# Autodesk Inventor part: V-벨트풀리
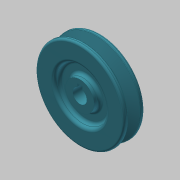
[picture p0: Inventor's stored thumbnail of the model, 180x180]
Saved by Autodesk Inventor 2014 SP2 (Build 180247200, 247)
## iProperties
Created: 2019-09
Part Number: V-벨트풀리
Material: 알루미늄 6061
Document SubType Name: Modeling
Designer: mduedu
Density: 1 g/cm^3
Appearance: 커뎃 파란색
Author: mduedu
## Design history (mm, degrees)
sketch "스케치1"
  geometry: L1 (-10, 0)-(10, 0); L2 (10, 0)-(10, 43.5); L3 (10, 43.5)-(-10, 43.5); L4 (-10, 43.5)-(-10, 0); L5 (0, 0)-(0, 43.5); L6 (-5.976, 43.5)-(-2.154, 31); L7 (-2.154, 31)-(2.154, 31); L8 (2.154, 31)-(5.976, 43.5); L9 (-10, 39)-(10, 39); 3 further points
  constraints: 18 end point, 8 point on line, 3 perpendicular, 2 midpoint, 2 parallel, 1 coincident, 1 horizontal, 1 other
  dimensions: "d0" = 87 diameter of L3 L1; "d3" = 12.5 distance between parallel lines of L7 L3; "d4" = 34 deg angle of L8 L6; "d5" = 20 distance between parallel lines of L2 L4; "d6" = 8 distance between parallel lines of L9 L7; "d7" = 9.2 distance of point (4.6, 39) point (-4.6, 39)
revolve "회전1" sketch "스케치1" stored, may be unused: angle "d8" = 90 deg
sketch "스케치2"
  geometry: C1 r 14 at (0, 0); C2 r 25 at (0, 0); 1 further point
  constraints: 2 centre point, 2 coincident
  dimensions: "d9" = 28 diameter of C1; "d10" = 50 diameter of C2
extrude "돌출1" cut sketch "스케치2" distance "d11" = 6; taper "d12" = 0 deg
fillet "모깎기1" dims "d13" = 3
fillet "모깎기2" dims "d14" = 3
fillet "모깎기3" dims "d15" = 0.5, "d16" = 1, "d17" = 2
sketch "스케치3"
  geometry: L1 (-2.5, 6.538)-(2.5, 6.538); L2 (2.5, 6.538)-(2.5, 9.3); L3 (2.5, 9.3)-(-2.5, 9.3); L4 (-2.5, 9.3)-(-2.5, 6.538); A1 r 7 centre (0, 0) between (-2.5, 6.538) and (2.5, 6.538); 1 further point
  constraints: 8 end point, 2 parallel, 2 point on circle, 1 centre point, 1 coincident, 1 horizontal, 1 perpendicular
  dimensions: "d18" = 14 diameter of A1; "d20" = 5 distance of L2.end L3.end; "d21" = 16.3 dimension on A1 L3
extrude "돌출2" cut sketch "스케치3" stored distance "d22" = 6; taper "d23" = 0 deg
node "솔리드1"
mirror "대칭1"
